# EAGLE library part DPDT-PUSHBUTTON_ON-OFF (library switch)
DPDT Pushbutton On-Off SWITCH Switch purchased from all electronics. This library was copied from switch-misc (PVA2R). Allelectronics CAT# PB-94
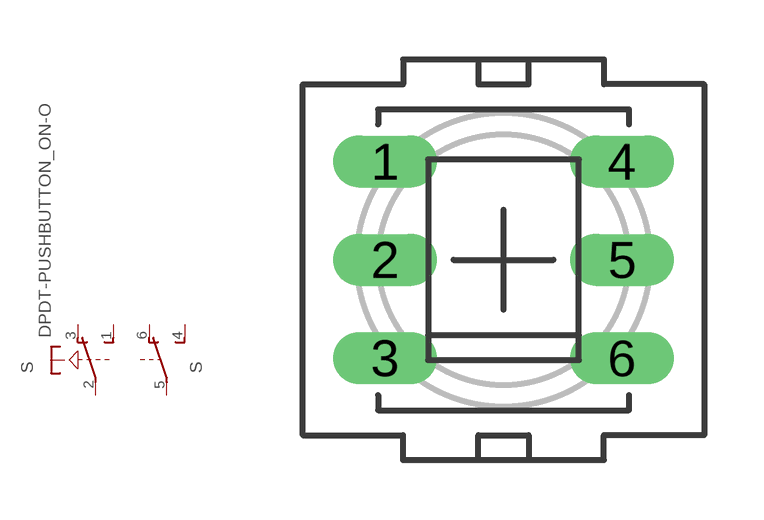
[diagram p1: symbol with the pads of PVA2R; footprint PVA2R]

Designator prefix S; gates 1=TRSU- 2=U-2

## DPDT-PUSHBUTTON_ON-OFF  [PVA2R]
1  1:S  pas
2  1:P  pas
3  1:O  pas
4  2:S  pas
5  2:P  pas
6  2:O  pas

## Footprint PVA2R (pad centres in mm)
ITT SWITCH
drill 0.813 long: 1 -2.997,2.489; 2 -2.997,0; 3 -2.997,-2.489; 4 2.997,2.489; 5 2.997,0; 6 2.997,-2.489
